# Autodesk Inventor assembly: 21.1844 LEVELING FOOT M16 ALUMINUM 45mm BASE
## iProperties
Created: 2007-03
Part Number: 21.1844 LEVELING FOOT M16 ALUMINUM 45mm BASE
Document SubType Name: Assembly
Designer: Andy Moles
Author: Andy Moles
